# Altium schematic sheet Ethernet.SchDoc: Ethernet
size A4; DocumentNumber: MB1165; Revision: C.1; SheetNumber: 7; SheetTotal: 17; Project: STM32469I-EVAL
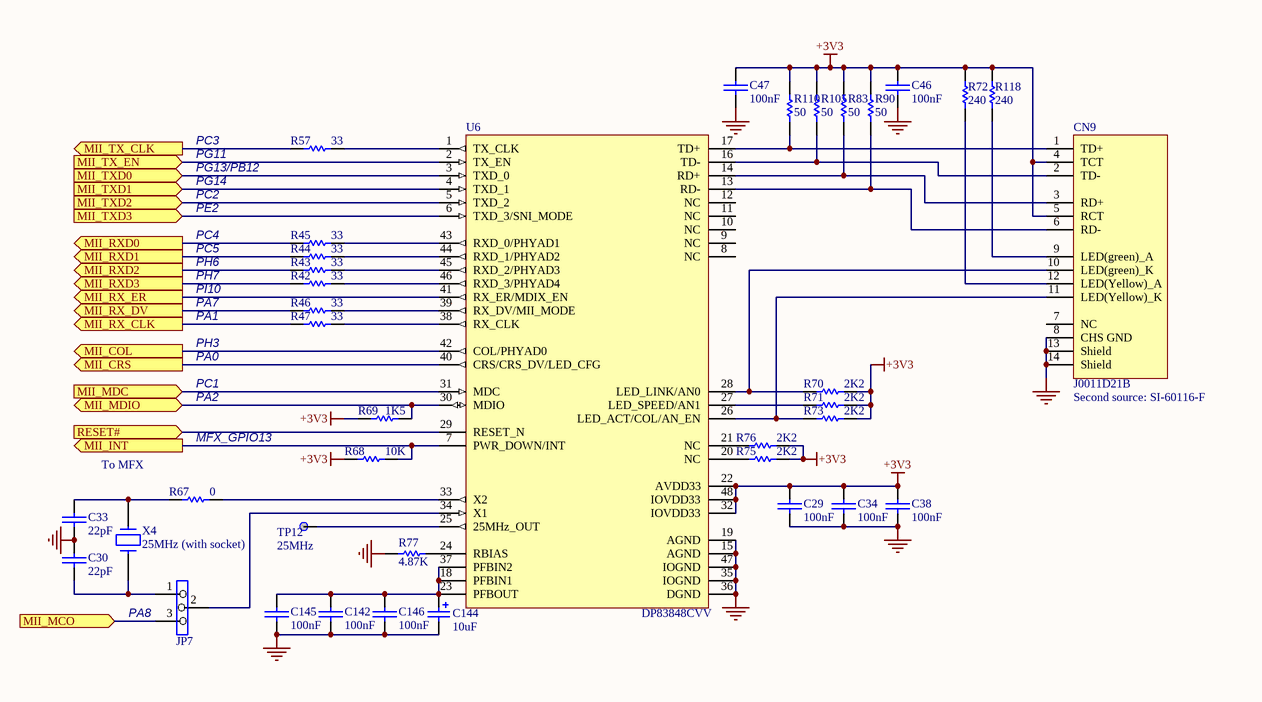
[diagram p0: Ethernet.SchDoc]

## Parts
C29  100nF  [0603C]
C30  22pF  [0603C]
C33  22pF  [0603C]
C34  100nF  [0603C]
C38  100nF  [0603C]
C46  100nF  [0603C]
C47  100nF  [0603C]
C142  100nF  [0603C]
C144  10uF  [TAN-A]
C145  100nF  [0603C]
C146  100nF  [0603C]
CN9  J0011D21B  [RJ45_J0011D01BNL]
JP7  (no value)  [SIP3]
R42  33  [0603R]
R43  33  [0603R]
R44  33  [0603R]
R45  33  [0603R]
R46  33  [0603R]
R47  33  [0603R]
R57  33  [0603R]
R67  0  [0603R]
R68  10K  [0603R]
R69  1K5  [0603R]
R70  2K2  [0603R]
R71  2K2  [0603R]
R72  240  [0603R]
R73  2K2  [0603R]
R75  2K2  [0603R]
R76  2K2  [0603R]
R77  4.87K  [0603R]
R83  50  [0603R]
R90  50  [0603R]
R105  50  [0603R]
R110  50  [0603R]
R118  240  [0603R]
TP12  25MHz  [TP]
U6  DP83848CVV  [LQFP48_0R5_9X9]
X4  25MHz (with socket)  [XTAL_socket]

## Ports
MII_COL (out), MII_CRS (out), MII_INT (out), MII_MCO (in), MII_MDC (in), MII_MDIO (bidir), MII_RX_CLK (out), MII_RX_DV (out), MII_RX_ER (out), MII_RXD0 (out), MII_RXD1 (out), MII_RXD2 (out), MII_RXD3 (out), MII_TX_CLK (out), MII_TX_EN (in), MII_TXD0 (in), MII_TXD1 (in), MII_TXD2 (in), MII_TXD3 (in), RESET# (in)

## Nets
+3V3: C29.1 C34.2 C38.2 C46.2 C47.2 CN9.4(TCT) CN9.5(RCT) R68.1 R69.2 R70.2 R71.2 R72.2 R73.2 R75.2 R76.2 R83.1 R90.1 R105.1 R110.1 R118.2 U6.22(AVDD33) U6.32(IOVDD33) U6.48(IOVDD33)
GND: C29.2 C30.2 C33.1 C34.1 C38.1 C46.1 C47.1 C142.1 C144.2 C145.2 C146.1 CN9.8(CHS_GND) CN9.13(Shield) CN9.14(Shield) R77.1 U6.15(AGND) U6.19(AGND) U6.35(IOGND) U6.36(DGND) U6.47(IOGND)
MII_COL: U6.42(COL/PHYAD0) ; port MII_COL
MII_CRS: U6.40(CRS/CRS_DV/LED_CFG) ; port MII_CRS
MII_INT: R68.2 U6.7(PWR_DOWN/INT) ; port MII_INT
MII_MCO: JP7.3 ; port MII_MCO
MII_MDC: U6.31(MDC) ; port MII_MDC
MII_MDIO: R69.1 U6.30(MDIO) ; port MII_MDIO
MII_RX_CLK: R47.2 ; port MII_RX_CLK
MII_RX_DV: R46.2 ; port MII_RX_DV
MII_RX_ER: U6.41(RX_ER/MDIX_EN) ; port MII_RX_ER
MII_RXD0: R45.2 ; port MII_RXD0
MII_RXD1: R44.2 ; port MII_RXD1
MII_RXD2: R43.2 ; port MII_RXD2
MII_RXD3: R42.2 ; port MII_RXD3
MII_TX_CLK: R57.2 ; port MII_TX_CLK
MII_TX_EN: U6.2(TX_EN) ; port MII_TX_EN
MII_TXD0: U6.3(TXD_0) ; port MII_TXD0
MII_TXD1: U6.4(TXD_1) ; port MII_TXD1
MII_TXD2: U6.5(TXD_2) ; port MII_TXD2
MII_TXD3: U6.6(TXD_3/SNI_MODE) ; port MII_TXD3
RESET#: U6.29(RESET_N) ; port RESET#
NetC30_1: C30.1 JP7.1 X4.1
NetC33_2: C33.2 R67.2 X4.2
NetC142_2: C142.2 C144.1 C145.1 C146.2 U6.18(PFBIN1) U6.23(PFBOUT) U6.37(PFBIN2)
NetCN9_1: CN9.1(TD+) R110.2 U6.17(TD+)
NetCN9_2: CN9.2(TD-) R105.2 U6.16(TD-)
NetCN9_3: CN9.3(RD+) R83.2 U6.14(RD+)
NetCN9_6: CN9.6(RD-) R90.2 U6.13(RD-)
NetCN9_9: CN9.9(LED(green)_A) R118.1
NetCN9_10: CN9.10(LED(green)_K) R70.1 U6.28(LED_LINK/AN0)
NetCN9_11: CN9.11(LED(Yellow)_K) R73.1 U6.26(LED_ACT/COL/AN_EN)
NetCN9_12: CN9.12(LED(Yellow)_A) R72.1
NetJP7_2: JP7.2 U6.34(X1)
NetR42_1: R42.1 U6.46(RXD_3/PHYAD4)
NetR43_1: R43.1 U6.45(RXD_2/PHYAD3)
NetR44_1: R44.1 U6.44(RXD_1/PHYAD2)
NetR45_1: R45.1 U6.43(RXD_0/PHYAD1)
NetR46_1: R46.1 U6.39(RX_DV/MII_MODE)
NetR47_1: R47.1 U6.38(RX_CLK)
NetR57_1: R57.1 U6.1(TX_CLK)
NetR67_1: R67.1 U6.33(X2)
NetR71_1: R71.1 U6.27(LED_SPEED/AN1)
NetR75_1: R75.1 U6.20(NC)
NetR76_1: R76.1 U6.21(NC)
NetR77_2: R77.2 U6.24(RBIAS)
NetTP12_1: TP12.1 U6.25(25MHz_OUT)

Not connected (* = marked no-connect by the designer): CN9 7(NC); U6 8(NC) 9(NC) 10(NC) 11(NC) 12(NC)

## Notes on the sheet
- PC3
- PG11
- PG13/PB12
- PG14
- PC2
- PE2
- PC4
- PC5
- PH6
- PH7
- PI10
- PA7
- PH3
- PA1
- PA0
- PC1
- PA2
- (near CN9) Second source: SI-60116-F
- To MFX
- MFX_GPIO13
- (near JP7) PA8

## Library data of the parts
C29 C30 C33 C34 C38 C46 C47 C142 C145 C146 = CAP: Capacitor
C144 = Cap Pol1: Polarized Capacitor (Radial)
JP7 = Jumper3
R42-R47 R57 R67-R73 R75-R77 R83 R90 R105 R110 R118 = Res1: Resistor; Value: 1K
TP12 = TP
X4 = CRYSTAL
